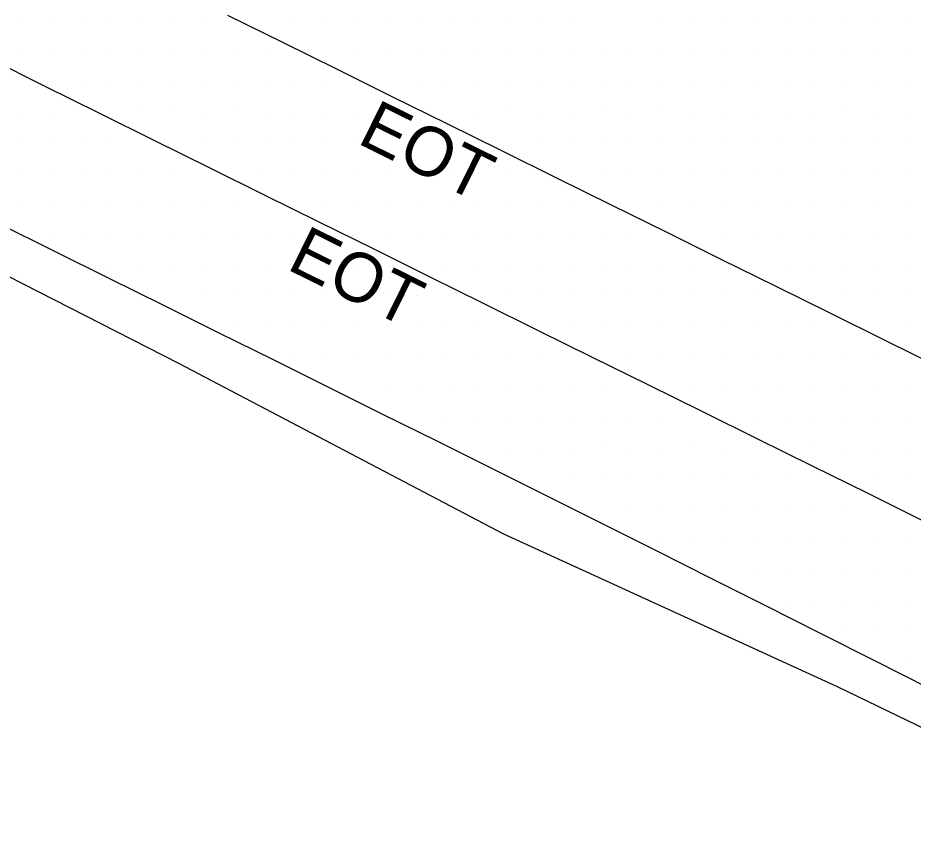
# Model space of a CAD drawing. Extents: x 2244337 to 2251208, y 199469 to 202984.
# Drawn here: x 2248891.4 to 2248964.6, y 200546.2 to 200612.9 of the extents above; entities that cross this region are included whole.
import ezdxf

# ---------------------------------------------------------------- set-up
doc = ezdxf.new("R2010")
doc.units = 0
for name, color, linetype in [('Exist DTM Scan Elevation Point', 7, 'Continuous'), ('Exist EOT Text', 7, 'Continuous'), ('Exist Roads EOP', 7, 'Continuous'), ('Exist Roads EOT', 7, 'Continuous')]:
    doc.layers.add(name, color=color, linetype=linetype)

msp = doc.modelspace()

# ---------------------------------------------------------------- linework, layer by layer
at = {"layer": 'Exist DTM Scan Elevation Point'}
for p, q in [((2248891.586, 200612.702), (2248891.586, 200612.702)), ((2248894.031, 200612.728), (2248894.031, 200612.728)), ((2248896.569, 200612.712), (2248896.569, 200612.712)), ((2248899.103, 200612.714), (2248899.103, 200612.714)), ((2248901.572, 200612.753), (2248901.572, 200612.753)), ((2248904.103, 200612.724), (2248904.103, 200612.724)), ((2248906.556, 200612.678), (2248906.556, 200612.678)), ((2248914.074, 200612.683), (2248914.074, 200612.683)), ((2248916.565, 200612.691), (2248916.565, 200612.691)), ((2248919.119, 200612.775), (2248919.119, 200612.775)), ((2248921.604, 200612.742), (2248921.604, 200612.742)), ((2248924.094, 200612.734), (2248924.094, 200612.734)), ((2248926.607, 200612.747), (2248926.607, 200612.747)), ((2248929.088, 200612.753), (2248929.088, 200612.753)), ((2248931.556, 200612.72), (2248931.556, 200612.72)), ((2248934.057, 200612.742), (2248934.057, 200612.742)), ((2248936.558, 200612.731), (2248936.558, 200612.731)), ((2248944.073, 200612.76), (2248944.073, 200612.76)), ((2248946.561, 200612.709), (2248946.561, 200612.709)), ((2248949.122, 200612.698), (2248949.122, 200612.698)), ((2248951.588, 200612.687), (2248951.588, 200612.687)), ((2248954.097, 200612.706), (2248954.097, 200612.706)), ((2248956.573, 200612.72), (2248956.573, 200612.72)), ((2248959.046, 200612.757), (2248959.046, 200612.757)), ((2248961.615, 200612.738), (2248961.615, 200612.738)), ((2248964.098, 200612.728), (2248964.098, 200612.728)), ((2248891.51, 200610.216), (2248891.51, 200610.216)), ((2248894.041, 200610.214), (2248894.041, 200610.214)), ((2248896.576, 200610.207), (2248896.576, 200610.207)), ((2248899.05, 200610.2), (2248899.05, 200610.2)), ((2248901.581, 200610.198), (2248901.581, 200610.198)), ((2248904.084, 200610.157), (2248904.084, 200610.157)), ((2248906.538, 200610.189), (2248906.538, 200610.189)), ((2248909.044, 200610.198), (2248909.044, 200610.198)), ((2248911.625, 200610.181), (2248911.625, 200610.181)), ((2248919.046, 200610.196), (2248919.046, 200610.196)), ((2248921.571, 200610.236), (2248921.571, 200610.236)), ((2248924.057, 200610.186), (2248924.057, 200610.186)), ((2248926.525, 200610.18), (2248926.525, 200610.18)), ((2248929.064, 200610.165), (2248929.064, 200610.165)), ((2248931.553, 200610.187), (2248931.553, 200610.187)), ((2248934.077, 200610.265), (2248934.077, 200610.265)), ((2248936.525, 200610.229), (2248936.525, 200610.229)), ((2248939.08, 200610.215), (2248939.08, 200610.215)), ((2248941.537, 200610.241), (2248941.537, 200610.241)), ((2248944.051, 200610.141), (2248944.051, 200610.141)), ((2248946.566, 200610.21), (2248946.566, 200610.21)), ((2248949.043, 200610.244), (2248949.043, 200610.244)), ((2248951.581, 200610.203), (2248951.581, 200610.203)), ((2248954.078, 200610.268), (2248954.078, 200610.268)), ((2248956.53, 200610.249), (2248956.53, 200610.249)), ((2248959.04, 200610.22), (2248959.04, 200610.22)), ((2248961.561, 200610.235), (2248961.561, 200610.235)), ((2248964.093, 200610.188), (2248964.093, 200610.188)), ((2248896.567, 200607.709), (2248896.567, 200607.709)), ((2248899.085, 200607.725), (2248899.085, 200607.725)), ((2248901.599, 200607.692), (2248901.599, 200607.692)), ((2248904.092, 200607.722), (2248904.092, 200607.722)), ((2248906.541, 200607.702), (2248906.541, 200607.702)), ((2248909.067, 200607.714), (2248909.067, 200607.714)), ((2248911.573, 200607.722), (2248911.573, 200607.722)), ((2248914.072, 200607.735), (2248914.072, 200607.735)), ((2248916.558, 200607.718), (2248916.558, 200607.718)), ((2248924.112, 200607.717), (2248924.112, 200607.717)), ((2248926.588, 200607.683), (2248926.588, 200607.683)), ((2248929.071, 200607.752), (2248929.071, 200607.752)), ((2248931.584, 200607.668), (2248931.584, 200607.668)), ((2248934.055, 200607.713), (2248934.055, 200607.713)), ((2248936.596, 200607.698), (2248936.596, 200607.698)), ((2248939.1, 200607.703), (2248939.1, 200607.703)), ((2248941.585, 200607.736), (2248941.585, 200607.736)), ((2248944.102, 200607.696), (2248944.102, 200607.696)), ((2248946.584, 200607.694), (2248946.584, 200607.694)), ((2248949.076, 200607.717), (2248949.076, 200607.717)), ((2248951.57, 200607.74), (2248951.57, 200607.74)), ((2248954.066, 200607.733), (2248954.066, 200607.733)), ((2248956.575, 200607.7), (2248956.575, 200607.7)), ((2248959.07, 200607.703), (2248959.07, 200607.703)), ((2248961.6, 200607.722), (2248961.6, 200607.722)), ((2248964.118, 200607.686), (2248964.118, 200607.686)), ((2248891.576, 200605.201), (2248891.576, 200605.201)), ((2248894.074, 200605.199), (2248894.074, 200605.199)), ((2248901.586, 200605.233), (2248901.586, 200605.233)), ((2248904.083, 200605.23), (2248904.083, 200605.23)), ((2248906.575, 200605.19), (2248906.575, 200605.19)), ((2248909.063, 200605.231), (2248909.063, 200605.231)), ((2248911.57, 200605.209), (2248911.57, 200605.209)), ((2248914.098, 200605.209), (2248914.098, 200605.209)), ((2248916.549, 200605.203), (2248916.549, 200605.203)), ((2248919.053, 200605.213), (2248919.053, 200605.213)), ((2248921.574, 200605.247), (2248921.574, 200605.247)), ((2248929.04, 200605.208), (2248929.04, 200605.208)), ((2248931.569, 200605.237), (2248931.569, 200605.237)), ((2248934.073, 200605.199), (2248934.073, 200605.199)), ((2248936.561, 200605.204), (2248936.561, 200605.204)), ((2248939.057, 200605.239), (2248939.057, 200605.239)), ((2248941.576, 200605.19), (2248941.576, 200605.19)), ((2248944.072, 200605.239), (2248944.072, 200605.239)), ((2248946.568, 200605.209), (2248946.568, 200605.209)), ((2248949.039, 200605.213), (2248949.039, 200605.213)), ((2248951.568, 200605.212), (2248951.568, 200605.212)), ((2248954.072, 200605.213), (2248954.072, 200605.213)), ((2248956.563, 200605.21), (2248956.563, 200605.21)), ((2248959.079, 200605.232), (2248959.079, 200605.232)), ((2248961.537, 200605.174), (2248961.537, 200605.174)), ((2248964.076, 200605.196), (2248964.076, 200605.196)), ((2248891.568, 200602.692), (2248891.568, 200602.692)), ((2248894.092, 200602.761), (2248894.092, 200602.761)), ((2248896.568, 200602.715), (2248896.568, 200602.715)), ((2248899.05, 200602.67), (2248899.05, 200602.67)), ((2248906.534, 200602.711), (2248906.534, 200602.711)), ((2248909.057, 200602.711), (2248909.057, 200602.711)), ((2248911.568, 200602.703), (2248911.568, 200602.703)), ((2248914.065, 200602.704), (2248914.065, 200602.704)), ((2248916.563, 200602.692), (2248916.563, 200602.692)), ((2248919.1, 200602.725), (2248919.1, 200602.725)), ((2248921.587, 200602.739), (2248921.587, 200602.739)), ((2248924.032, 200602.72), (2248924.032, 200602.72)), ((2248926.615, 200602.676), (2248926.615, 200602.676)), ((2248934.053, 200602.699), (2248934.053, 200602.699)), ((2248936.556, 200602.714), (2248936.556, 200602.714)), ((2248939.097, 200602.734), (2248939.097, 200602.734)), ((2248941.574, 200602.703), (2248941.574, 200602.703)), ((2248944.111, 200602.719), (2248944.111, 200602.719)), ((2248946.591, 200602.709), (2248946.591, 200602.709)), ((2248949.024, 200602.689), (2248949.024, 200602.689)), ((2248951.592, 200602.718), (2248951.592, 200602.718)), ((2248954.052, 200602.706), (2248954.052, 200602.706)), ((2248956.583, 200602.714), (2248956.583, 200602.714)), ((2248959.114, 200602.712), (2248959.114, 200602.712)), ((2248961.575, 200602.754), (2248961.575, 200602.754)), ((2248964.074, 200602.696), (2248964.074, 200602.696)), ((2248891.541, 200600.162), (2248891.541, 200600.162)), ((2248894.154, 200600.251), (2248894.154, 200600.251)), ((2248896.549, 200600.244), (2248896.549, 200600.244)), ((2248899.081, 200600.199), (2248899.081, 200600.199)), ((2248901.58, 200600.196), (2248901.58, 200600.196)), ((2248904.091, 200600.209), (2248904.091, 200600.209)), ((2248911.534, 200600.194), (2248911.534, 200600.194)), ((2248914.085, 200600.193), (2248914.085, 200600.193)), ((2248916.596, 200600.213), (2248916.596, 200600.213)), ((2248919.084, 200600.246), (2248919.084, 200600.246)), ((2248921.563, 200600.173), (2248921.563, 200600.173)), ((2248924.049, 200600.237), (2248924.049, 200600.237)), ((2248926.598, 200600.195), (2248926.598, 200600.195)), ((2248929.059, 200600.183), (2248929.059, 200600.183)), ((2248931.567, 200600.231), (2248931.567, 200600.231)), ((2248939.096, 200600.231), (2248939.096, 200600.231)), ((2248941.607, 200600.207), (2248941.607, 200600.207)), ((2248944.064, 200600.207), (2248944.064, 200600.207)), ((2248946.585, 200600.201), (2248946.585, 200600.201)), ((2248949.059, 200600.17), (2248949.059, 200600.17)), ((2248951.604, 200600.215), (2248951.604, 200600.215)), ((2248954.04, 200600.188), (2248954.04, 200600.188)), ((2248956.621, 200600.203), (2248956.621, 200600.203)), ((2248959.069, 200600.221), (2248959.069, 200600.221)), ((2248961.601, 200600.218), (2248961.601, 200600.218)), ((2248964.138, 200600.226), (2248964.138, 200600.226)), ((2248891.589, 200597.731), (2248891.589, 200597.731)), ((2248894.102, 200597.723), (2248894.102, 200597.723)), ((2248896.555, 200597.738), (2248896.555, 200597.738)), ((2248899.074, 200597.672), (2248899.074, 200597.672)), ((2248901.533, 200597.717), (2248901.533, 200597.717)), ((2248904.053, 200597.693), (2248904.053, 200597.693)), ((2248906.602, 200597.72), (2248906.602, 200597.72)), ((2248909.06, 200597.706), (2248909.06, 200597.706)), ((2248916.603, 200597.751), (2248916.603, 200597.751)), ((2248919.055, 200597.684), (2248919.055, 200597.684)), ((2248921.517, 200597.684), (2248921.517, 200597.684)), ((2248924.053, 200597.654), (2248924.053, 200597.654)), ((2248926.595, 200597.724), (2248926.595, 200597.724)), ((2248929.036, 200597.727), (2248929.036, 200597.727)), ((2248931.523, 200597.732), (2248931.523, 200597.732)), ((2248934.029, 200597.692), (2248934.029, 200597.692)), ((2248936.576, 200597.732), (2248936.576, 200597.732)), ((2248944.016, 200597.682), (2248944.016, 200597.682)), ((2248946.57, 200597.708), (2248946.57, 200597.708)), ((2248949.084, 200597.723), (2248949.084, 200597.723)), ((2248951.596, 200597.676), (2248951.596, 200597.676)), ((2248954.076, 200597.712), (2248954.076, 200597.712)), ((2248956.541, 200597.699), (2248956.541, 200597.699)), ((2248959.066, 200597.702), (2248959.066, 200597.702)), ((2248961.57, 200597.711), (2248961.57, 200597.711)), ((2248964.026, 200597.718), (2248964.026, 200597.718)), ((2248894.066, 200595.176), (2248894.066, 200595.176)), ((2248896.583, 200595.215), (2248896.583, 200595.215)), ((2248899.098, 200595.199), (2248899.098, 200595.199)), ((2248901.594, 200595.19), (2248901.594, 200595.19)), ((2248904.066, 200595.234), (2248904.066, 200595.234)), ((2248906.586, 200595.174), (2248906.586, 200595.174)), ((2248909.086, 200595.258), (2248909.086, 200595.258)), ((2248911.582, 200595.195), (2248911.582, 200595.195)), ((2248914.072, 200595.197), (2248914.072, 200595.197)), ((2248921.572, 200595.171), (2248921.572, 200595.171)), ((2248924.074, 200595.23), (2248924.074, 200595.23)), ((2248926.55, 200595.153), (2248926.55, 200595.153)), ((2248929.064, 200595.255), (2248929.064, 200595.255)), ((2248931.577, 200595.2), (2248931.577, 200595.2)), ((2248934.078, 200595.222), (2248934.078, 200595.222)), ((2248936.597, 200595.199), (2248936.597, 200595.199)), ((2248939.07, 200595.216), (2248939.07, 200595.216)), ((2248941.555, 200595.194), (2248941.555, 200595.194)), ((2248949.046, 200595.229), (2248949.046, 200595.229)), ((2248951.631, 200595.2), (2248951.631, 200595.2)), ((2248954.053, 200595.199), (2248954.053, 200595.199)), ((2248956.57, 200595.161), (2248956.57, 200595.161)), ((2248959.069, 200595.247), (2248959.069, 200595.247)), ((2248961.546, 200595.181), (2248961.546, 200595.181)), ((2248964.11, 200595.258), (2248964.11, 200595.258)), ((2248899.105, 200592.724), (2248899.105, 200592.724)), ((2248901.602, 200592.749), (2248901.602, 200592.749)), ((2248906.601, 200592.735), (2248906.601, 200592.735)), ((2248914.073, 200592.708), (2248914.073, 200592.708)), ((2248936.545, 200592.741), (2248936.545, 200592.741)), ((2248939.088, 200592.733), (2248939.088, 200592.733)), ((2248941.629, 200592.725), (2248941.629, 200592.725)), ((2248944.084, 200592.741), (2248944.084, 200592.741)), ((2248956.574, 200592.73), (2248956.574, 200592.73)), ((2248959.1, 200592.709), (2248959.1, 200592.709)), ((2248961.651, 200592.725), (2248961.651, 200592.725)), ((2248964.111, 200592.75), (2248964.111, 200592.75)), ((2248904.096, 200592.679), (2248904.096, 200592.679)), ((2248909.085, 200592.688), (2248909.085, 200592.688)), ((2248911.606, 200592.645), (2248911.606, 200592.645)), ((2248916.548, 200592.699), (2248916.548, 200592.699)), ((2248919.072, 200592.706), (2248919.072, 200592.706)), ((2248926.553, 200592.697), (2248926.553, 200592.697)), ((2248929.11, 200592.676), (2248929.11, 200592.676)), ((2248931.635, 200592.688), (2248931.635, 200592.688)), ((2248934.074, 200592.68), (2248934.074, 200592.68)), ((2248946.552, 200592.684), (2248946.552, 200592.684)), ((2248954.115, 200592.682), (2248954.115, 200592.682)), ((2248906.577, 200590.218), (2248906.577, 200590.218)), ((2248909.08, 200590.208), (2248909.08, 200590.208)), ((2248911.605, 200590.202), (2248911.605, 200590.202)), ((2248914.072, 200590.211), (2248914.072, 200590.211)), ((2248916.526, 200590.233), (2248916.526, 200590.233)), ((2248919.059, 200590.199), (2248919.059, 200590.199)), ((2248921.567, 200590.215), (2248921.567, 200590.215)), ((2248924.07, 200590.197), (2248924.07, 200590.197)), ((2248931.63, 200590.196), (2248931.63, 200590.196)), ((2248934.09, 200590.205), (2248934.09, 200590.205)), ((2248936.531, 200590.211), (2248936.531, 200590.211)), ((2248939.096, 200590.23), (2248939.096, 200590.23)), ((2248941.606, 200590.239), (2248941.606, 200590.239)), ((2248944.092, 200590.174), (2248944.092, 200590.174)), ((2248946.623, 200590.225), (2248946.623, 200590.225)), ((2248949.08, 200590.193), (2248949.08, 200590.193)), ((2248951.611, 200590.187), (2248951.611, 200590.187)), ((2248959.088, 200590.203), (2248959.088, 200590.203)), ((2248961.56, 200590.239), (2248961.56, 200590.239)), ((2248964.047, 200590.2), (2248964.047, 200590.2)), ((2248909.053, 200587.687), (2248909.053, 200587.687)), ((2248911.625, 200587.703), (2248911.625, 200587.703)), ((2248914.097, 200587.718), (2248914.097, 200587.718)), ((2248916.517, 200587.711), (2248916.517, 200587.711)), ((2248919.059, 200587.71), (2248919.059, 200587.71)), ((2248921.565, 200587.717), (2248921.565, 200587.717)), ((2248924.032, 200587.735), (2248924.032, 200587.735)), ((2248926.537, 200587.659), (2248926.537, 200587.659)), ((2248929.056, 200587.707), (2248929.056, 200587.707)), ((2248936.59, 200587.74), (2248936.59, 200587.74)), ((2248939.068, 200587.703), (2248939.068, 200587.703)), ((2248941.577, 200587.718), (2248941.577, 200587.718)), ((2248944.107, 200587.671), (2248944.107, 200587.671)), ((2248946.567, 200587.691), (2248946.567, 200587.691)), ((2248949.011, 200587.667), (2248949.011, 200587.667)), ((2248951.536, 200587.699), (2248951.536, 200587.699)), ((2248954.089, 200587.725), (2248954.089, 200587.725)), ((2248956.605, 200587.682), (2248956.605, 200587.682)), ((2248964.124, 200587.718), (2248964.124, 200587.718)), ((2248914.082, 200585.192), (2248914.082, 200585.192)), ((2248916.56, 200585.208), (2248916.56, 200585.208)), ((2248919.054, 200585.225), (2248919.054, 200585.225)), ((2248921.564, 200585.213), (2248921.564, 200585.213)), ((2248924.081, 200585.203), (2248924.081, 200585.203)), ((2248926.574, 200585.207), (2248926.574, 200585.207)), ((2248929.087, 200585.264), (2248929.087, 200585.264)), ((2248931.506, 200585.248), (2248931.506, 200585.248)), ((2248934.076, 200585.186), (2248934.076, 200585.186)), ((2248941.538, 200585.211), (2248941.538, 200585.211)), ((2248944.098, 200585.258), (2248944.098, 200585.258)), ((2248946.582, 200585.213), (2248946.582, 200585.213)), ((2248949.078, 200585.226), (2248949.078, 200585.226)), ((2248951.531, 200585.213), (2248951.531, 200585.213)), ((2248954.039, 200585.203), (2248954.039, 200585.203)), ((2248956.58, 200585.165), (2248956.58, 200585.165)), ((2248959.1, 200585.173), (2248959.1, 200585.173)), ((2248961.566, 200585.215), (2248961.566, 200585.215)), ((2248921.59, 200582.732), (2248921.59, 200582.732)), ((2248924.045, 200582.715), (2248924.045, 200582.715)), ((2248926.606, 200582.72), (2248926.606, 200582.72)), ((2248929.091, 200582.703), (2248929.091, 200582.703)), ((2248931.594, 200582.715), (2248931.594, 200582.715)), ((2248934.081, 200582.709), (2248934.081, 200582.709)), ((2248936.623, 200582.713), (2248936.623, 200582.713)), ((2248939.054, 200582.745), (2248939.054, 200582.745)), ((2248946.565, 200582.698), (2248946.565, 200582.698)), ((2248949.092, 200582.695), (2248949.092, 200582.695)), ((2248951.579, 200582.691), (2248951.579, 200582.691)), ((2248954.06, 200582.736), (2248954.06, 200582.736)), ((2248956.612, 200582.661), (2248956.612, 200582.661)), ((2248959.097, 200582.678), (2248959.097, 200582.678)), ((2248961.53, 200582.715), (2248961.53, 200582.715)), ((2248964.095, 200582.68), (2248964.095, 200582.68)), ((2248926.548, 200580.193), (2248926.548, 200580.193)), ((2248929.09, 200580.201), (2248929.09, 200580.201)), ((2248931.539, 200580.201), (2248931.539, 200580.201)), ((2248934.06, 200580.207), (2248934.06, 200580.207)), ((2248936.594, 200580.197), (2248936.594, 200580.197)), ((2248939.05, 200580.21), (2248939.05, 200580.21)), ((2248941.597, 200580.214), (2248941.597, 200580.214)), ((2248944.079, 200580.187), (2248944.079, 200580.187)), ((2248951.572, 200580.157), (2248951.572, 200580.157)), ((2248954.067, 200580.238), (2248954.067, 200580.238)), ((2248956.601, 200580.192), (2248956.601, 200580.192)), ((2248959.096, 200580.213), (2248959.096, 200580.213)), ((2248961.536, 200580.246), (2248961.536, 200580.246)), ((2248964.075, 200580.187), (2248964.075, 200580.187)), ((2248931.581, 200577.722), (2248931.581, 200577.722)), ((2248934.066, 200577.714), (2248934.066, 200577.714)), ((2248936.586, 200577.709), (2248936.586, 200577.709)), ((2248939.022, 200577.756), (2248939.022, 200577.756)), ((2248941.565, 200577.618), (2248941.565, 200577.618)), ((2248944.011, 200577.685), (2248944.011, 200577.685)), ((2248946.599, 200577.74), (2248946.599, 200577.74)), ((2248949.112, 200577.705), (2248949.112, 200577.705)), ((2248956.579, 200577.742), (2248956.579, 200577.742)), ((2248959.11, 200577.713), (2248959.11, 200577.713)), ((2248961.572, 200577.662), (2248961.572, 200577.662)), ((2248964.078, 200577.689), (2248964.078, 200577.689)), ((2248936.626, 200575.221), (2248936.626, 200575.221)), ((2248939.093, 200575.18), (2248939.093, 200575.18)), ((2248941.601, 200575.206), (2248941.601, 200575.206)), ((2248944.094, 200575.188), (2248944.094, 200575.188)), ((2248946.566, 200575.236), (2248946.566, 200575.236)), ((2248949.124, 200575.226), (2248949.124, 200575.226)), ((2248951.591, 200575.244), (2248951.591, 200575.244)), ((2248954.11, 200575.237), (2248954.11, 200575.237)), ((2248961.586, 200575.197), (2248961.586, 200575.197)), ((2248964.081, 200575.201), (2248964.081, 200575.201)), ((2248941.554, 200572.711), (2248941.554, 200572.711)), ((2248944.026, 200572.734), (2248944.026, 200572.734)), ((2248946.571, 200572.739), (2248946.571, 200572.739)), ((2248949.087, 200572.721), (2248949.087, 200572.721)), ((2248951.523, 200572.718), (2248951.523, 200572.718)), ((2248954.087, 200572.693), (2248954.087, 200572.693)), ((2248956.548, 200572.715), (2248956.548, 200572.715)), ((2248959.076, 200572.697), (2248959.076, 200572.697)), ((2248944.067, 200570.237), (2248944.067, 200570.237)), ((2248946.564, 200570.189), (2248946.564, 200570.189)), ((2248949.038, 200570.188), (2248949.038, 200570.188)), ((2248951.631, 200570.214), (2248951.631, 200570.214)), ((2248954.071, 200570.254), (2248954.071, 200570.254)), ((2248956.581, 200570.234), (2248956.581, 200570.234)), ((2248959.101, 200570.227), (2248959.101, 200570.227)), ((2248961.583, 200570.189), (2248961.583, 200570.189)), ((2248964.087, 200570.21), (2248964.087, 200570.21)), ((2248951.619, 200567.731), (2248951.619, 200567.731)), ((2248954.1, 200567.73), (2248954.1, 200567.73)), ((2248956.585, 200567.722), (2248956.585, 200567.722)), ((2248959.121, 200567.712), (2248959.121, 200567.712)), ((2248961.568, 200567.704), (2248961.568, 200567.704)), ((2248964.092, 200567.691), (2248964.092, 200567.691)), ((2248954.074, 200565.207), (2248954.074, 200565.207)), ((2248956.578, 200565.19), (2248956.578, 200565.19)), ((2248959.088, 200565.152), (2248959.088, 200565.152)), ((2248961.546, 200565.168), (2248961.546, 200565.168)), ((2248964.097, 200565.202), (2248964.097, 200565.202)), ((2248959.07, 200562.704), (2248959.07, 200562.704)), ((2248961.554, 200562.721), (2248961.554, 200562.721)), ((2248964.093, 200562.721), (2248964.093, 200562.721)), ((2248964.056, 200560.236), (2248964.056, 200560.236))]:
    msp.add_line(p, q, dxfattribs=at)
at = {"layer": 'Exist Roads EOP'}
msp.add_lwpolyline([(2249496.132, 200291.911), (2249469.236, 200305.199), (2249442.332, 200318.471), (2249415.42, 200331.728), (2249388.432, 200344.848), (2249361.558, 200358.183), (2249334.769, 200371.688), (2249307.957, 200385.146), (2249281.076, 200398.465), (2249254.008, 200411.433), (2249227.177, 200424.851), (2249200.319, 200438.183), (2249173.414, 200451.455), (2249146.512, 200464.743), (2249119.646, 200478.019), (2249092.784, 200491.38), (2249065.794, 200504.549), (2249038.929, 200517.901), (2249012.244, 200531.616), (2248985.449, 200545.142), (2248958.433, 200558.195), (2248931.163, 200570.687), (2248904.596, 200584.639), (2248877.888, 200598.28)], dxfattribs=at)
at = {"layer": 'Exist Roads EOT'}
for points in [[(2248908.57, 200613.145), (2248913.051, 200610.927), (2248917.532, 200608.709), (2248922.013, 200606.491), (2248926.495, 200604.273), (2248930.976, 200602.055), (2248935.457, 200599.838), (2248939.939, 200597.621), (2248944.421, 200595.404), (2248948.902, 200593.187), (2248953.384, 200590.97), (2248957.866, 200588.753), (2248962.347, 200586.537), (2248966.829, 200584.32)], [(2248889.152, 200609.549), (2248893.633, 200607.33), (2248898.113, 200605.111), (2248902.594, 200602.892), (2248907.075, 200600.672), (2248911.555, 200598.453), (2248916.036, 200596.234), (2248920.516, 200594.015), (2248924.997, 200591.796), (2248929.478, 200589.577), (2248933.958, 200587.358), (2248938.44, 200585.142), (2248942.922, 200582.926), (2248947.404, 200580.71), (2248951.886, 200578.494), (2248956.368, 200576.278), (2248960.851, 200574.061), (2248965.332, 200571.844)], [(2248889.894, 200596.075), (2248894.376, 200593.858), (2248898.854, 200591.634), (2248903.332, 200589.411), (2248907.811, 200587.187), (2248912.289, 200584.963), (2248916.767, 200582.74), (2248921.245, 200580.516), (2248925.724, 200578.292), (2248930.202, 200576.069), (2248934.674, 200573.832), (2248939.146, 200571.596), (2248943.611, 200569.346), (2248948.077, 200567.096), (2248952.542, 200564.847), (2248957.007, 200562.597), (2248961.472, 200560.347), (2248965.937, 200558.097), (2248970.403, 200555.847), (2248974.868, 200553.597), (2248979.333, 200551.347), (2248983.798, 200549.097), (2248988.269, 200546.858), (2248992.739, 200544.618)]]:
    msp.add_lwpolyline(points, dxfattribs=at)

# ---------------------------------------------------------------- texts
at = {"layer": 'Exist EOT Text'}
for rotation, p in [(333.66513, (2248919.071, 200602.709)), (333.65242, (2248913.309, 200592.409))]:
    msp.add_text('EOT', height=4.02, rotation=rotation, dxfattribs=at).set_placement(p)

doc.saveas('drawing.dxf')
